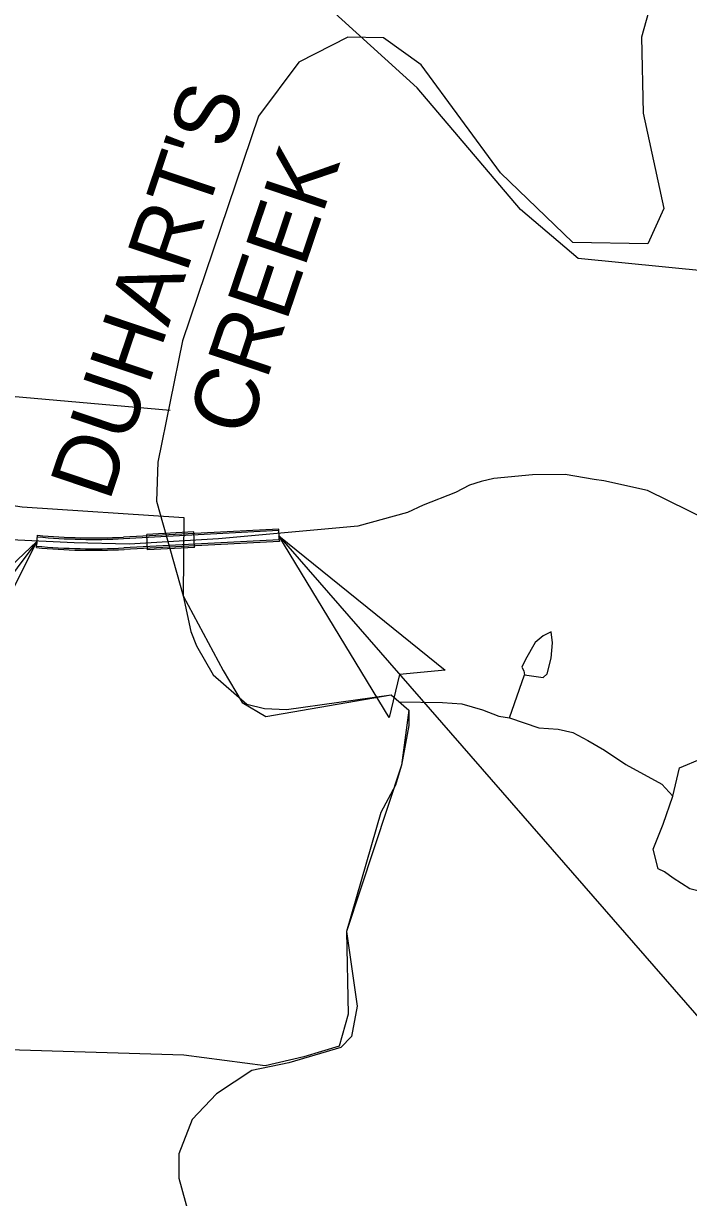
# Model space of a CAD drawing. Extents: x 1373043 to 1375788, y 550128 to 553055.
# Drawn here: x 1373306.4 to 1373360.4, y 550589.5 to 550684.8 of the extents above; entities that cross this region are included whole.
import ezdxf

# ---------------------------------------------------------------- set-up
doc = ezdxf.new("R2010")
doc.units = 0
for name, color, linetype in [('Old_Level_32', 7, 'Continuous'), ('Old_Level_48', 7, 'Continuous'), ('Old_Level_50', 7, 'Continuous'), ('Old_Level_59', 7, 'Continuous'), ('Old_Level_62', 7, 'Continuous'), ('Prop Dimension', 7, 'Continuous'), ('Prop EOT', 7, 'Continuous'), ('Prop Horizontal Alignment Tick Small', 7, 'Continuous'), ('Prop Paved Shoulder', 7, 'Continuous'), ('Prop Roadway Bridge', 7, 'Continuous'), ('Prop Terminator CELL', 7, 'Continuous')]:
    doc.layers.add(name, color=color, linetype=linetype)

msp = doc.modelspace()

# ---------------------------------------------------------------- linework, layer by layer
at = {"layer": 'Old_Level_32'}
for points in [[(1373318.17, 550642.731), (1373315.016, 550642.559), (1373310.542, 550642.649), (1373305.421, 550642.899), (1373300.839, 550643.654), (1373292.022, 550645.478), (1373290.567, 550645.764), (1373288.828, 550646.378), (1373286.067, 550647.195), (1373284.182, 550647.979), (1373281.363, 550649.546), (1373279.522, 550650.671), (1373276.965, 550652.102), (1373273.82, 550653.584), (1373269.602, 550654.882), (1373266.15, 550655.424), (1373259.707, 550655.526), (1373253.518, 550655.549), (1373249.535, 550655.597), (1373246.193, 550655.553)], [(1373375.415, 550636.791), (1373374.723, 550637.221), (1373369.24, 550640.364), (1373363.782, 550643.642), (1373357.106, 550646.911), (1373353.573, 550647.682), (1373352.778, 550647.811), (1373350.432, 550648.193), (1373347.785, 550648.183), (1373344.627, 550647.869), (1373343.607, 550647.637), (1373342.662, 550647.341), (1373341.509, 550646.734), (1373338.905, 550645.721), (1373337.632, 550645.116), (1373333.575, 550644.001), (1373322.272, 550642.974), (1373318.17, 550642.731)]]:
    msp.add_lwpolyline(points, dxfattribs=at)
at = {"layer": 'Old_Level_48'}
for p, q in [((1373332.8, 550604.388), (1373332.078, 550601.785)), ((1373319.453, 550601.041), (1373291.136, 550601.909)), ((1373332.078, 550601.785), (1373329.192, 550600.917)), ((1373326.066, 550600.173), (1373319.453, 550601.041)), ((1373329.192, 550600.917), (1373326.066, 550600.173))]:
    msp.add_line(p, q, dxfattribs=at)
for points in [[(1373372.484, 550663.667), (1373351.492, 550665.744), (1373346.79, 550669.727), (1373338.393, 550679.596), (1373329.661, 550687.56), (1373321.264, 550696.217), (1373317.066, 550702.969), (1373312.196, 550697.256), (1373273.31, 550698.107), (1373267.779, 550688.19), (1373260.324, 550675.669), (1373262.969, 550674.057), (1373265.75, 550669.807)], [(1373265.75, 550669.807), (1373263.33, 550668.231), (1373261.286, 550671.33), (1373258.278, 550672.671), (1373257.077, 550670.71), (1373249.502, 550657.818), (1373256.115, 550657.942), (1373266.182, 550657.867), (1373274.914, 550657.001), (1373278.441, 550655.443), (1373283.143, 550651.807), (1373287.173, 550648.863), (1373293.555, 550647.478), (1373306.318, 550645.574), (1373319.463, 550644.718), (1373319.393, 550638.355), (1373322.639, 550632.281), (1373324.202, 550629.677), (1373326.126, 550628.562), (1373336.287, 550630.297), (1373337.729, 550629.057), (1373337.128, 550624.595), (1373332.679, 550611.082), (1373332.8, 550604.388)]]:
    msp.add_lwpolyline(points, dxfattribs=at)
at = {"layer": 'Old_Level_50'}
msp.add_line((1373318.13, 550642.745), (1373318.13, 550642.745), dxfattribs=at)
at = {"layer": 'Old_Level_59'}
msp.add_lwpolyline([(1373357.705, 550687.626), (1373356.629, 550683.73), (1373356.764, 550677.549), (1373358.447, 550669.793), (1373357.15, 550666.928), (1373351.051, 550667.054), (1373345.167, 550672.693), (1373338.727, 550681.481), (1373335.67, 550683.654), (1373332.776, 550683.716), (1373328.804, 550681.7), (1373325.511, 550677.292), (1373319.353, 550659.051), (1373317.334, 550649.193), (1373317.244, 550646.049), (1373319.393, 550638.355), (1373320.03, 550635.449), (1373320.48, 550634.281), (1373321.828, 550631.945), (1373324.563, 550629.553), (1373326.011, 550629.213), (1373327.808, 550629.124), (1373336.287, 550630.297), (1373337.729, 550629.057), (1373337.729, 550627.818), (1373337.128, 550624.595), (1373336.647, 550622.983), (1373335.445, 550620.752), (1373332.679, 550611.082), (1373333.527, 550605.015), (1373333.078, 550602.567), (1373332.198, 550601.661), (1373327.99, 550600.421), (1373324.984, 550599.801), (1373322.112, 550597.896), (1373320.135, 550595.83), (1373319.056, 550593.045), (1373319.056, 550591.069), (1373319.865, 550588.104)], dxfattribs=at)
at = {"layer": 'Old_Level_62'}
msp.add_line((1373345.906, 550628.429), (1373347.114, 550631.933), dxfattribs=at)
for points in [[(1373283.987, 550657.989), (1373284.478, 550657.824), (1373284.969, 550657.659), (1373285.445, 550657.462), (1373285.909, 550657.236), (1373286.369, 550656.997), (1373286.826, 550656.755), (1373287.286, 550656.519), (1373287.756, 550656.306), (1373288.255, 550656.164), (1373288.764, 550656.087), (1373289.276, 550656.016), (1373289.789, 550655.951), (1373318.346, 550653.434)], [(1373347.114, 550631.933), (1373348.633, 550631.713), (1373348.95, 550632.023), (1373349.286, 550633.276), (1373349.389, 550634.532), (1373349.278, 550635.417), (1373348.625, 550635.114), (1373347.994, 550634.562), (1373347.216, 550633.192), (1373346.894, 550632.569), (1373347.069, 550632.249), (1373347.114, 550631.933)], [(1373336.928, 550629.746), (1373340.451, 550629.675), (1373342.026, 550629.578), (1373343.721, 550629.104), (1373345.029, 550628.574), (1373345.906, 550628.429)], [(1373345.906, 550628.429), (1373348.293, 550627.621), (1373349.869, 550627.524), (1373351.051, 550627.25), (1373352.254, 550626.594), (1373353.607, 550625.813), (1373355.341, 550624.64), (1373358.283, 550623.064), (1373359.178, 550622.089)], [(1373359.178, 550622.089), (1373359.716, 550624.373), (1373361.529, 550625.141), (1373362.046, 550625.067), (1373363.094, 550624.479), (1373367.028, 550622.128), (1373369.886, 550620.303), (1373371.878, 550619.192), (1373374.924, 550617.616), (1373376.25, 550616.767), (1373376.855, 550615.998), (1373377.456, 550614.977), (1373377.774, 550614.151), (1373377.808, 550613.269), (1373377.924, 550612.636)], [(1373377.924, 550612.636), (1373376.965, 550612.468), (1373375.78, 550612.62), (1373374.473, 550613.214), (1373373.27, 550613.866), (1373371.468, 550614.222), (1373369.124, 550614.583), (1373366.567, 550614.7), (1373363.772, 550614.571), (1373361.629, 550614.275), (1373360.551, 550614.544), (1373359.189, 550615.42), (1373358.501, 550615.94), (1373357.968, 550616.178), (1373357.565, 550617.79), (1373358.372, 550619.805), (1373359.178, 550622.089)]]:
    msp.add_lwpolyline(points, dxfattribs=at)
at = {"layer": 'Prop Dimension'}
for p, q in [((1373307.528, 550642.765), (1373235.141, 550546.227)), ((1373327.169, 550643.231), (1373389.199, 550572.032))]:
    msp.add_line(p, q, dxfattribs=at)
at = {"layer": 'Prop EOT'}
for p, q in [((1373327.172, 550643.644), (1373314.555, 550642.992)), ((1373327.191, 550643.267), (1373327.172, 550643.644)), ((1373307.481, 550642.263), (1373307.576, 550643.267)), ((1373327.211, 550642.889), (1373314.594, 550642.237)), ((1373327.211, 550642.889), (1373327.191, 550643.267))]:
    msp.add_line(p, q, dxfattribs=at)
for radius in [47.974, 48.731]:
    msp.add_arc((1373312.079, 550690.903), radius, 264.59986, 272.95848, dxfattribs=at)
at = {"layer": 'Prop Horizontal Alignment Tick Small'}
msp.add_line((1373307.528, 550642.765), (1373307.514, 550642.608), dxfattribs=at)
at = {"layer": 'Prop Paved Shoulder'}
for p, q in [((1373327.165, 550643.77), (1373314.548, 550643.118)), ((1373327.172, 550643.644), (1373327.165, 550643.77)), ((1373327.217, 550642.764), (1373314.601, 550642.112)), ((1373327.211, 550642.889), (1373327.217, 550642.764))]:
    msp.add_line(p, q, dxfattribs=at)
for radius in [47.848, 48.856]:
    msp.add_arc((1373312.079, 550690.903), radius, 264.59986, 272.95848, dxfattribs=at)
at = {"layer": 'Prop Roadway Bridge'}
for p, q in [((1373320.262, 550643.54), (1373316.446, 550643.342)), ((1373316.511, 550642.084), (1373316.446, 550643.342)), ((1373320.327, 550642.281), (1373320.262, 550643.54)), ((1373320.327, 550642.281), (1373316.511, 550642.084))]:
    msp.add_line(p, q, dxfattribs=at)
at = {"layer": 'Prop Terminator CELL'}
for points in [[(1373294.98, 550630.913), (1373307.528, 550642.765), (1373299.687, 550627.266), (1373298.571, 550630.819)], [(1373336.134, 550628.481), (1373327.169, 550643.231), (1373340.685, 550632.321), (1373336.977, 550631.973)], [(1373336.134, 550628.481), (1373327.169, 550643.231), (1373340.685, 550632.321), (1373336.977, 550631.973)]]:
    msp.add_lwpolyline(points, close=True, dxfattribs=at)

# ---------------------------------------------------------------- texts
at = {"layer": 'Prop Dimension'}
for s, p in [("DUHART'S ", (1373313.395, 550645.914)), ('CREEK', (1373324.581, 550651.075))]:
    msp.add_text(s, height=5.1673, rotation=71.34319, dxfattribs=at).set_placement(p)

doc.saveas('drawing.dxf')
